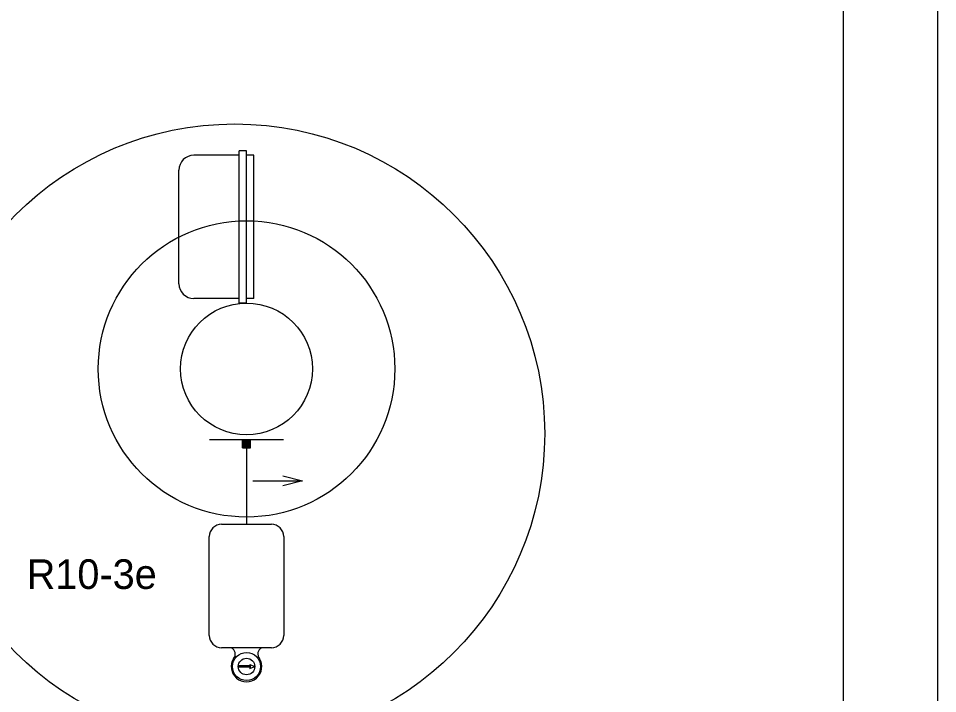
# Model space of a CAD drawing. Extents: x 1370050 to 1370716, y 380076 to 380502.
# Drawn here: x 1370623.4 to 1370716.4, y 380198.5 to 380266.8 of the extents above; entities that cross this region are included whole.
import ezdxf

# ---------------------------------------------------------------- set-up
doc = ezdxf.new("R2010")
doc.units = 0
for name, color, linetype in [('R_Border', 7, 'Continuous'), ('R_No Plot', 7, 'Continuous'), ('T_Drafting', 7, 'Continuous')]:
    doc.layers.add(name, color=color, linetype=linetype)

msp = doc.modelspace()

# ---------------------------------------------------------------- linework, layer by layer
at = {"layer": 'R_Border'}
msp.add_line((1370706.846, 380083.656), (1370706.846, 380494.576), dxfattribs=at)
at = {"layer": 'R_No Plot'}
msp.add_lwpolyline([(1370049.671, 380502.366), (1370716.351, 380502.366), (1370716.351, 380075.69), (1370049.671, 380075.69)], close=True, dxfattribs=at)
at = {"layer": 'T_Drafting'}
for p, q in [((1370645.69, 380252.957), (1370641.106, 380252.957)), ((1370645.69, 380237.998), (1370645.69, 380253.415)), ((1370646.44, 380253.415), (1370645.69, 380253.415)), ((1370646.44, 380237.998), (1370646.44, 380253.415)), ((1370647.19, 380252.957), (1370646.44, 380252.957)), ((1370647.19, 380238.457), (1370647.19, 380252.957)), ((1370639.606, 380239.957), (1370639.606, 380251.457)), ((1370645.69, 380238.457), (1370641.106, 380238.457)), ((1370646.44, 380237.998), (1370645.69, 380237.998)), ((1370647.19, 380238.457), (1370646.44, 380238.457)), ((1370650.19, 380224.165), (1370642.69, 380224.165)), ((1370646.023, 380223.332), (1370646.023, 380224.165)), ((1370646.023, 380223.338), (1370646.85, 380224.165)), ((1370646.023, 380223.352), (1370646.836, 380224.165)), ((1370646.023, 380223.366), (1370646.822, 380224.165)), ((1370646.023, 380223.38), (1370646.808, 380224.165)), ((1370646.023, 380223.394), (1370646.794, 380224.165)), ((1370646.023, 380223.408), (1370646.78, 380224.165)), ((1370646.023, 380223.423), (1370646.766, 380224.165)), ((1370646.023, 380223.437), (1370646.751, 380224.165)), ((1370646.023, 380223.451), (1370646.737, 380224.165)), ((1370646.023, 380223.465), (1370646.723, 380224.165)), ((1370646.023, 380223.479), (1370646.709, 380224.165)), ((1370646.023, 380223.493), (1370646.695, 380224.165)), ((1370646.023, 380223.507), (1370646.681, 380224.165)), ((1370646.023, 380223.522), (1370646.667, 380224.165)), ((1370646.023, 380223.536), (1370646.653, 380224.165)), ((1370646.023, 380223.55), (1370646.638, 380224.165)), ((1370646.023, 380223.564), (1370646.624, 380224.165)), ((1370646.023, 380223.578), (1370646.61, 380224.165)), ((1370646.023, 380223.592), (1370646.596, 380224.165)), ((1370646.023, 380223.606), (1370646.582, 380224.165)), ((1370646.023, 380223.621), (1370646.568, 380224.165)), ((1370646.023, 380223.635), (1370646.554, 380224.165)), ((1370646.023, 380223.649), (1370646.539, 380224.165)), ((1370646.023, 380223.663), (1370646.525, 380224.165)), ((1370646.023, 380223.677), (1370646.511, 380224.165)), ((1370646.023, 380223.691), (1370646.497, 380224.165)), ((1370646.023, 380223.705), (1370646.483, 380224.165)), ((1370646.023, 380223.72), (1370646.469, 380224.165)), ((1370646.023, 380223.734), (1370646.455, 380224.165)), ((1370646.023, 380223.748), (1370646.44, 380224.165)), ((1370646.023, 380223.762), (1370646.426, 380224.165)), ((1370646.023, 380223.776), (1370646.412, 380224.165)), ((1370646.023, 380223.79), (1370646.398, 380224.165)), ((1370646.023, 380223.804), (1370646.384, 380224.165)), ((1370646.023, 380223.819), (1370646.37, 380224.165)), ((1370646.023, 380223.833), (1370646.356, 380224.165)), ((1370646.023, 380223.847), (1370646.341, 380224.165)), ((1370646.023, 380223.861), (1370646.327, 380224.165)), ((1370646.023, 380223.875), (1370646.313, 380224.165)), ((1370646.023, 380223.889), (1370646.299, 380224.165)), ((1370646.023, 380223.903), (1370646.285, 380224.165)), ((1370646.023, 380223.918), (1370646.271, 380224.165)), ((1370646.023, 380223.932), (1370646.257, 380224.165)), ((1370646.023, 380223.946), (1370646.242, 380224.165)), ((1370646.023, 380223.96), (1370646.228, 380224.165)), ((1370646.023, 380223.974), (1370646.214, 380224.165)), ((1370646.023, 380223.988), (1370646.2, 380224.165)), ((1370646.023, 380224.002), (1370646.186, 380224.165)), ((1370646.023, 380224.017), (1370646.172, 380224.165)), ((1370646.023, 380224.031), (1370646.158, 380224.165)), ((1370646.023, 380224.045), (1370646.143, 380224.165)), ((1370646.023, 380224.059), (1370646.129, 380224.165)), ((1370646.023, 380224.073), (1370646.115, 380224.165)), ((1370646.023, 380224.087), (1370646.101, 380224.165)), ((1370646.023, 380224.101), (1370646.087, 380224.165)), ((1370646.023, 380224.116), (1370646.073, 380224.165)), ((1370646.023, 380224.13), (1370646.059, 380224.165)), ((1370646.023, 380224.144), (1370646.044, 380224.165)), ((1370646.023, 380224.158), (1370646.03, 380224.165)), ((1370646.031, 380223.332), (1370646.856, 380224.157)), ((1370646.045, 380223.332), (1370646.856, 380224.143)), ((1370646.06, 380223.332), (1370646.856, 380224.129)), ((1370646.074, 380223.332), (1370646.856, 380224.115)), ((1370646.088, 380223.332), (1370646.856, 380224.1)), ((1370646.102, 380223.332), (1370646.856, 380224.086)), ((1370646.116, 380223.332), (1370646.856, 380224.072)), ((1370646.13, 380223.332), (1370646.856, 380224.058)), ((1370646.144, 380223.332), (1370646.856, 380224.044)), ((1370646.159, 380223.332), (1370646.856, 380224.03)), ((1370646.173, 380223.332), (1370646.856, 380224.016)), ((1370646.187, 380223.332), (1370646.856, 380224.001)), ((1370646.201, 380223.332), (1370646.856, 380223.987)), ((1370646.215, 380223.332), (1370646.856, 380223.973)), ((1370646.229, 380223.332), (1370646.856, 380223.959)), ((1370646.243, 380223.332), (1370646.856, 380223.945)), ((1370646.258, 380223.332), (1370646.856, 380223.931)), ((1370646.272, 380223.332), (1370646.856, 380223.917)), ((1370646.286, 380223.332), (1370646.856, 380223.902)), ((1370646.3, 380223.332), (1370646.856, 380223.888)), ((1370646.314, 380223.332), (1370646.856, 380223.874)), ((1370646.328, 380223.332), (1370646.856, 380223.86)), ((1370646.342, 380223.332), (1370646.856, 380223.846)), ((1370646.357, 380223.332), (1370646.856, 380223.832)), ((1370646.371, 380223.332), (1370646.856, 380223.818)), ((1370646.385, 380223.332), (1370646.856, 380223.803)), ((1370646.399, 380223.332), (1370646.856, 380223.789)), ((1370646.413, 380223.332), (1370646.856, 380223.775)), ((1370646.427, 380223.332), (1370646.856, 380223.761)), ((1370646.441, 380223.332), (1370646.856, 380223.747)), ((1370646.456, 380223.332), (1370646.856, 380223.733)), ((1370646.47, 380223.332), (1370646.856, 380223.719)), ((1370646.856, 380223.332), (1370646.856, 380224.165)), ((1370646.023, 380223.332), (1370646.856, 380223.332)), ((1370646.44, 380223.332), (1370646.44, 380215.596)), ((1370646.484, 380223.332), (1370646.856, 380223.704)), ((1370646.498, 380223.332), (1370646.856, 380223.69)), ((1370646.512, 380223.332), (1370646.856, 380223.676)), ((1370646.526, 380223.332), (1370646.856, 380223.662)), ((1370646.54, 380223.332), (1370646.856, 380223.648)), ((1370646.555, 380223.332), (1370646.856, 380223.634)), ((1370646.569, 380223.332), (1370646.856, 380223.62)), ((1370646.583, 380223.332), (1370646.856, 380223.605)), ((1370646.597, 380223.332), (1370646.856, 380223.591)), ((1370646.611, 380223.332), (1370646.856, 380223.577)), ((1370646.625, 380223.332), (1370646.856, 380223.563)), ((1370646.639, 380223.332), (1370646.856, 380223.549)), ((1370646.654, 380223.332), (1370646.856, 380223.535)), ((1370646.668, 380223.332), (1370646.856, 380223.521)), ((1370646.682, 380223.332), (1370646.856, 380223.506)), ((1370646.696, 380223.332), (1370646.856, 380223.492)), ((1370646.71, 380223.332), (1370646.856, 380223.478)), ((1370646.724, 380223.332), (1370646.856, 380223.464)), ((1370646.738, 380223.332), (1370646.856, 380223.45)), ((1370646.753, 380223.332), (1370646.856, 380223.436)), ((1370646.767, 380223.332), (1370646.856, 380223.422)), ((1370646.781, 380223.332), (1370646.856, 380223.407)), ((1370646.795, 380223.332), (1370646.856, 380223.393)), ((1370646.809, 380223.332), (1370646.856, 380223.379)), ((1370646.823, 380223.332), (1370646.856, 380223.365)), ((1370646.837, 380223.332), (1370646.856, 380223.351)), ((1370646.852, 380223.332), (1370646.856, 380223.337)), ((1370647.084, 380219.998), (1370652.117, 380219.998)), ((1370643.923, 380215.596), (1370648.956, 380215.596)), ((1370642.673, 380204.346), (1370642.673, 380214.346)), ((1370650.206, 380214.346), (1370650.206, 380204.346)), ((1370648.956, 380203.096), (1370643.923, 380203.096)), ((1370645.612, 380201.271), (1370645.612, 380201.121)), ((1370646.867, 380201.271), (1370645.612, 380201.271)), ((1370646.867, 380201.121), (1370645.612, 380201.121)), ((1370646.767, 380201.396), (1370647.273, 380201.196)), ((1370646.867, 380201.271), (1370646.767, 380201.396)), ((1370646.767, 380200.996), (1370647.273, 380201.196)), ((1370646.767, 380200.996), (1370646.867, 380201.121))]:
    msp.add_line(p, q, dxfattribs=at)
msp.add_lwpolyline([(1370650.117, 380220.498), (1370652.117, 380219.998), (1370650.117, 380219.498)], dxfattribs=at)
for centre, radius in [((1370645.25, 380224.778), 31.351), ((1370646.44, 380231.332), 15), ((1370646.44, 380231.332), 6.667), ((1370646.44, 380201.196), 1.417), ((1370646.44, 380201.196), 0.833)]:
    msp.add_circle(centre, radius, dxfattribs=at)
for centre, radius, start, end in [((1370641.106, 380251.457), 1.5, 90, 180), ((1370641.106, 380239.957), 1.5, 180, 270), ((1370643.923, 380214.346), 1.25, 90, 180), ((1370648.956, 380214.346), 1.25, 0, 90), ((1370643.923, 380204.346), 1.25, 180, 270), ((1370648.956, 380204.346), 1.25, 270, 0), ((1370644.6, 380202.462), 0.7, 318.19721, 64.80442), ((1370648.279, 380202.462), 0.7, 115.19558, 221.80279), ((1370646.44, 380201.196), 1.542, 148.74024, 227.49336), ((1370646.44, 380201.196), 1.542, 148.74024, 31.25976), ((1370646.44, 380201.196), 1.542, 312.50664, 31.25976)]:
    msp.add_arc(centre, radius, start, end, dxfattribs=at)

# ---------------------------------------------------------------- texts
msp.add_text('R10-3e', height=3, dxfattribs=at).set_placement((1370624.202, 380209.051))

doc.saveas('drawing.dxf')
